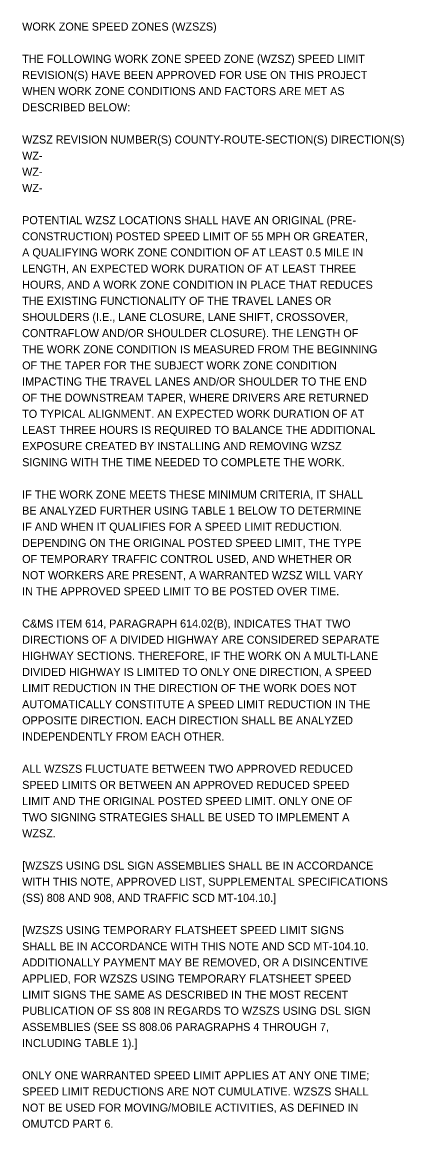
# Model space of a CAD drawing. Extents: x -9 to 65.1, y -15.6 to 23.2.
# Drawn here: x 39.08 to 45.69, y 3.98 to 23.17 of the extents above; entities that cross this region are included whole.
import ezdxf

# ---------------------------------------------------------------- set-up
doc = ezdxf.new("R2010")
doc.units = 0
doc.layers.add('SH_Text', color=7, linetype='Continuous')

msp = doc.modelspace()

# ---------------------------------------------------------------- texts
at = {"layer": 'SH_Text'}
for s, p in [('WORK ZONE SPEED ZONES (WZSZS)', (39.076, 23.02)), ('THE FOLLOWING WORK ZONE SPEED ZONE (WZSZ) SPEED LIMIT', (39.076, 22.46)), ('REVISION(S) HAVE BEEN APPROVED FOR USE ON THIS PROJECT', (39.076, 22.18)), ('WHEN WORK ZONE CONDITIONS AND FACTORS ARE MET AS', (39.076, 21.9)), ('DESCRIBED BELOW:', (39.076, 21.62)), ('WZSZ REVISION NUMBER(S) COUNTY-ROUTE-SECTION(S) DIRECTION(S)', (39.076, 21.06)), ('WZ-', (39.076, 20.78)), ('WZ-', (39.076, 20.5)), ('WZ-', (39.076, 20.22)), ('POTENTIAL WZSZ LOCATIONS SHALL HAVE AN ORIGINAL (PRE-', (39.076, 19.66)), ('CONSTRUCTION) POSTED SPEED LIMIT OF 55 MPH OR GREATER,', (39.076, 19.38)), ('A QUALIFYING WORK ZONE CONDITION OF AT LEAST 0.5 MILE IN', (39.076, 19.1)), ('LENGTH, AN EXPECTED WORK DURATION OF AT LEAST THREE', (39.076, 18.82)), ('HOURS, AND A WORK ZONE CONDITION IN PLACE THAT REDUCES', (39.076, 18.54)), ('THE EXISTING FUNCTIONALITY OF THE TRAVEL LANES OR', (39.076, 18.26)), ('SHOULDERS (I.E., LANE CLOSURE, LANE SHIFT, CROSSOVER,', (39.076, 17.98)), ('CONTRAFLOW AND/OR SHOULDER CLOSURE). THE LENGTH OF', (39.076, 17.7)), ('THE WORK ZONE CONDITION IS MEASURED FROM THE BEGINNING', (39.076, 17.42)), ('OF THE TAPER FOR THE SUBJECT WORK ZONE CONDITION', (39.076, 17.14)), ('IMPACTING THE TRAVEL LANES AND/OR SHOULDER TO THE END', (39.076, 16.86)), ('OF THE DOWNSTREAM TAPER, WHERE DRIVERS ARE RETURNED', (39.076, 16.58)), ('TO TYPICAL ALIGNMENT. AN EXPECTED WORK DURATION OF AT', (39.076, 16.3)), ('LEAST THREE HOURS IS REQUIRED TO BALANCE THE ADDITIONAL', (39.076, 16.02)), ('EXPOSURE CREATED BY INSTALLING AND REMOVING WZSZ', (39.076, 15.74)), ('SIGNING WITH THE TIME NEEDED TO COMPLETE THE WORK.', (39.076, 15.46)), ('IF THE WORK ZONE MEETS THESE MINIMUM CRITERIA, IT SHALL', (39.076, 14.9)), ('BE ANALYZED FURTHER USING TABLE 1 BELOW TO DETERMINE', (39.076, 14.62)), ('IF AND WHEN IT QUALIFIES FOR A SPEED LIMIT REDUCTION.', (39.076, 14.34)), ('DEPENDING ON THE ORIGINAL POSTED SPEED LIMIT, THE TYPE', (39.076, 14.06)), ('OF TEMPORARY TRAFFIC CONTROL USED, AND WHETHER OR', (39.076, 13.78)), ('NOT WORKERS ARE PRESENT, A WARRANTED WZSZ WILL VARY', (39.076, 13.5)), ('IN THE APPROVED SPEED LIMIT TO BE POSTED OVER TIME.', (39.076, 13.22)), ('C&MS ITEM 614, PARAGRAPH 614.02(B), INDICATES THAT TWO', (39.076, 12.66)), ('DIRECTIONS OF A DIVIDED HIGHWAY ARE CONSIDERED SEPARATE', (39.076, 12.38)), ('HIGHWAY SECTIONS. THEREFORE, IF THE WORK ON A MULTI-LANE', (39.076, 12.1)), ('DIVIDED HIGHWAY IS LIMITED TO ONLY ONE DIRECTION, A SPEED', (39.076, 11.82)), ('LIMIT REDUCTION IN THE DIRECTION OF THE WORK DOES NOT', (39.076, 11.54)), ('AUTOMATICALLY CONSTITUTE A SPEED LIMIT REDUCTION IN THE', (39.076, 11.26)), ('OPPOSITE DIRECTION. EACH DIRECTION SHALL BE ANALYZED', (39.076, 10.98)), ('INDEPENDENTLY FROM EACH OTHER.', (39.076, 10.7)), ('ALL WZSZS FLUCTUATE BETWEEN TWO APPROVED REDUCED', (39.076, 10.14)), ('SPEED LIMITS OR BETWEEN AN APPROVED REDUCED SPEED', (39.076, 9.86)), ('LIMIT AND THE ORIGINAL POSTED SPEED LIMIT. ONLY ONE OF', (39.076, 9.58)), ('TWO SIGNING STRATEGIES SHALL BE USED TO IMPLEMENT A', (39.076, 9.3)), ('WZSZ.', (39.076, 9.02)), ('[WZSZS USING DSL SIGN ASSEMBLIES SHALL BE IN ACCORDANCE', (39.076, 8.46)), ('WITH THIS NOTE, APPROVED LIST, SUPPLEMENTAL SPECIFICATIONS', (39.076, 8.18)), ('(SS) 808 AND 908, AND TRAFFIC SCD MT-104.10.]', (39.076, 7.9)), ('[WZSZS USING TEMPORARY FLATSHEET SPEED LIMIT SIGNS', (39.076, 7.34)), ('SHALL BE IN ACCORDANCE WITH THIS NOTE AND SCD MT-104.10.', (39.076, 7.06)), ('ADDITIONALLY PAYMENT MAY BE REMOVED, OR A DISINCENTIVE', (39.076, 6.78)), ('APPLIED, FOR WZSZS USING TEMPORARY FLATSHEET SPEED', (39.076, 6.5)), ('LIMIT SIGNS THE SAME AS DESCRIBED IN THE MOST RECENT', (39.076, 6.22)), ('PUBLICATION OF SS 808 IN REGARDS TO WZSZS USING DSL SIGN', (39.076, 5.94)), ('ASSEMBLIES (SEE SS 808.06 PARAGRAPHS 4 THROUGH 7,', (39.076, 5.66)), ('INCLUDING TABLE 1).]', (39.076, 5.38)), ('ONLY ONE WARRANTED SPEED LIMIT APPLIES AT ANY ONE TIME;', (39.076, 4.82)), ('SPEED LIMIT REDUCTIONS ARE NOT CUMULATIVE. WZSZS SHALL', (39.076, 4.54)), ('NOT BE USED FOR MOVING/MOBILE ACTIVITIES, AS DEFINED IN', (39.076, 4.26)), ('OMUTCD PART 6.', (39.076, 3.98))]:
    msp.add_text(s, height=0.14, dxfattribs=at).set_placement(p)

doc.saveas('drawing.dxf')
